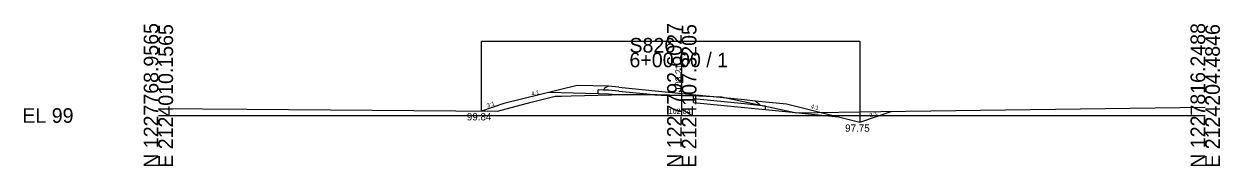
# Model space of a CAD drawing. Extents: x 2118382 to 2118616, y 1213030 to 1222057.
# Drawn here: x 2118381.9 to 2118610.4, y 1216530.1 to 1216557.3 of the extents above; entities that cross this region are included whole.
import ezdxf

# ---------------------------------------------------------------- set-up
doc = ezdxf.new("R2010")
doc.units = 0
for name, color, linetype in [('XS_CELL', 7, 'Continuous'), ('XS_M_DITCH', 7, 'Continuous'), ('XS_P_FINISHED_GRADE', 7, 'Continuous'), ('XS_P_FINISHED_GRADE_ELEV_TX', 7, 'Continuous'), ('XS_P_SUBGRADE_GRANULAR', 7, 'Continuous'), ('XS_P_SUBGRADE_LEVELING', 7, 'Continuous'), ('XS_P_SUBGRADE_PAVEMENT', 7, 'Continuous'), ('XS_P_TX_DCH', 7, 'Continuous'), ('XS_P_TX_FS_BS', 7, 'Continuous'), ('XS_X_GROUND', 7, 'Continuous'), ('XS_X_GROUND_TX', 7, 'Continuous')]:
    doc.layers.add(name, color=color, linetype=linetype)

msp = doc.modelspace()

# ---------------------------------------------------------------- linework, layer by layer
at = {"layer": 'XS_CELL'}
for p, q in [((2118507.6, 1216539.8), (2118507.6, 1216551.84)), ((2118407.6, 1216539.8), (2118507.6, 1216539.8)), ((2118507.6, 1216539.8), (2118607.6, 1216539.8))]:
    msp.add_line(p, q, dxfattribs=at)
at = {"layer": 'XS_M_DITCH'}
for p, q in [((2118469.31, 1216540.64), (2118469.31, 1216554.01)), ((2118469.31, 1216554.01), (2118541.6, 1216554.01)), ((2118541.6, 1216554.01), (2118541.6, 1216538.55))]:
    msp.add_line(p, q, dxfattribs=at)
at = {"layer": 'XS_P_FINISHED_GRADE'}
for p, q in [((2118487.6, 1216545.56), (2118473.6, 1216542.07)), ((2118493.6, 1216545.39), (2118487.6, 1216545.56)), ((2118495.6, 1216545.2), (2118493.6, 1216545.39)), ((2118495.6, 1216545.2), (2118507.6, 1216544.01)), ((2118507.6, 1216544.01), (2118519.6, 1216542.83)), ((2118473.6, 1216542.07), (2118469.31, 1216540.64)), ((2118519.6, 1216542.83), (2118521.6, 1216542.63)), ((2118521.6, 1216542.63), (2118527.6, 1216542.04)), ((2118527.6, 1216542.04), (2118541.6, 1216538.55)), ((2118541.6, 1216538.55), (2118547.82, 1216540.61))]:
    msp.add_line(p, q, dxfattribs=at)
at = {"layer": 'XS_P_SUBGRADE_GRANULAR'}
for p, q in [((2118491.6, 1216543.95), (2118482.21, 1216544.22)), ((2118491.6, 1216543.95), (2118491.6, 1216544.7)), ((2118492.65, 1216544.67), (2118491.6, 1216544.7)), ((2118493.6, 1216543.89), (2118491.6, 1216543.95)), ((2118494.98, 1216543.76), (2118493.6, 1216543.89)), ((2118497.87, 1216543.81), (2118494.98, 1216543.76)), ((2118500.15, 1216543.78), (2118497.87, 1216543.81)), ((2118502.88, 1216543.73), (2118500.15, 1216543.78)), ((2118509.86, 1216542.29), (2118509.86, 1216543.04)), ((2118509.86, 1216542.29), (2118519.6, 1216541.33)), ((2118519.6, 1216541.33), (2118523.6, 1216540.93)), ((2118522.43, 1216541.8), (2118523.6, 1216541.68)), ((2118523.6, 1216540.93), (2118523.6, 1216541.68)), ((2118523.6, 1216540.93), (2118537.53, 1216539.56))]:
    msp.add_line(p, q, dxfattribs=at)
at = {"layer": 'XS_P_SUBGRADE_LEVELING'}
for q in [(2118502.88, 1216543.73), (2118509.86, 1216543.6)]:
    msp.add_line((2118507.6, 1216543.64), q, dxfattribs=at)
at = {"layer": 'XS_P_SUBGRADE_PAVEMENT'}
for p, q in [((2118493.6, 1216545.39), (2118492.85, 1216545.01)), ((2118492.85, 1216545.01), (2118492.65, 1216544.67)), ((2118493.6, 1216544.64), (2118492.65, 1216544.67)), ((2118495.6, 1216544.45), (2118493.6, 1216544.64)), ((2118495.6, 1216544.45), (2118502.88, 1216543.73)), ((2118509.86, 1216543.04), (2118509.86, 1216543.6)), ((2118509.86, 1216543.04), (2118519.6, 1216542.08)), ((2118519.6, 1216542.08), (2118522.43, 1216541.8)), ((2118521.6, 1216542.63), (2118522.25, 1216542.11)), ((2118522.25, 1216542.11), (2118522.43, 1216541.8))]:
    msp.add_line(p, q, dxfattribs=at)
at = {"layer": 'XS_X_GROUND'}
for p, q in [((2118478.85, 1216542.32), (2118483.38, 1216543.51)), ((2118483.38, 1216543.51), (2118484.64, 1216543.53)), ((2118484.64, 1216543.53), (2118486.48, 1216543.58)), ((2118486.48, 1216543.58), (2118496.74, 1216543.79)), ((2118496.74, 1216543.79), (2118497.87, 1216543.81)), ((2118497.87, 1216543.81), (2118502.44, 1216543.73)), ((2118502.44, 1216543.73), (2118503.64, 1216543.71)), ((2118503.64, 1216543.71), (2118507.6, 1216543.64)), ((2118507.6, 1216543.64), (2118509.86, 1216543.6)), ((2118509.86, 1216543.6), (2118510.86, 1216543.56)), ((2118510.86, 1216543.56), (2118515.2, 1216543.36)), ((2118515.2, 1216543.36), (2118523.29, 1216541.65)), ((2118407.6, 1216541.17), (2118424.47, 1216541.03)), ((2118424.47, 1216541.03), (2118472.37, 1216540.61)), ((2118472.37, 1216540.61), (2118478.85, 1216542.32)), ((2118523.29, 1216541.65), (2118529.5, 1216540.33)), ((2118545.62, 1216540.59), (2118607.6, 1216541.4)), ((2118529.5, 1216540.33), (2118545.62, 1216540.59))]:
    msp.add_line(p, q, dxfattribs=at)

# ---------------------------------------------------------------- texts
at = {"layer": 'XS_CELL'}
for s, p in [('N 1227768.9565', (2118407.6, 1216529.8)), ('E 2124010.1565', (2118410.4, 1216529.8)), ('N 1227792.6027', (2118507.6, 1216529.8)), ('E 2124107.3205', (2118510.4, 1216529.8)), ('N 1227816.2488', (2118607.6, 1216529.8)), ('E 2124204.4846', (2118610.4, 1216529.8))]:
    msp.add_text(s, height=2.8, rotation=90, dxfattribs=at).set_placement(p)
for s, p in [('S826', (2118497.6, 1216551.84)), ('6+00.00 / 1', (2118497.6, 1216549.04)), ('EL 99', (2118381.6, 1216538.4))]:
    msp.add_text(s, height=2.8, dxfattribs=at).set_placement(p)
at = {"layer": 'XS_P_FINISHED_GRADE_ELEV_TX'}
msp.add_text(' 103.21', height=1.25, rotation=90, dxfattribs=at).set_placement((2118507.6, 1216544.01))
at = {"layer": 'XS_P_TX_DCH'}
for s, p in [('99.84', (2118466.53, 1216538.86)), ('97.75', (2118538.81, 1216536.69))]:
    msp.add_text(s, height=1.4, dxfattribs=at).set_placement(p)
at = {"layer": 'XS_P_TX_FS_BS'}
for s, rotation, p in [('4:1', 14.0157, (2118478.97, 1216543.54)), ('3:1', 18.4087, (2118470.49, 1216541.3)), ('4:1', 345.9882, (2118532.18, 1216541.23)), ('3:1', 18.4038, (2118543.61, 1216539.41))]:
    msp.add_text(s, height=0.8, rotation=rotation, dxfattribs=at).set_placement(p)
at = {"layer": 'XS_X_GROUND_TX'}
msp.add_text('102.84', height=1, dxfattribs=at).set_placement((2118505.07, 1216540.11))

doc.saveas('drawing.dxf')
